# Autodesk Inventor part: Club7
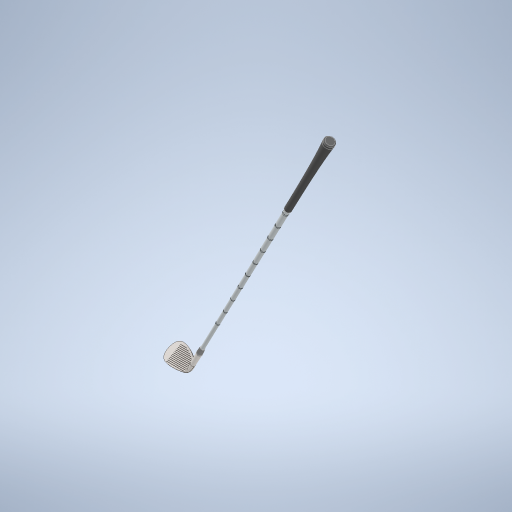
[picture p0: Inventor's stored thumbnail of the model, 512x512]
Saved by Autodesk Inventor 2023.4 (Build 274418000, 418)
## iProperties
Created: 2012-07
Part Number: Club7
Material: Générique
Document SubType Name: Modeling
Designer: bruno
Density: 1 g/cm^3
Appearance: Par défaut
Mass: 100.859 g
Surface Area: 1086.9 cm^2
Volume: 100.859 cm^3
Sending System: SolidWorks 2011
Last Author: Steen
Last Saved: 2012-07-11
Author: bruno
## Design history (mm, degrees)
node "Spalding 62 degree wedge.SLDPRT"
node "Solide1"
feature "Spalding 62degree v2-1-solid1"
node "Solide2"
feature "Shaft-1-solid1"
node "Solide3"
feature "Ferrule-1-solid1"
node "Solide4"
feature "Grip-1-solid1"
